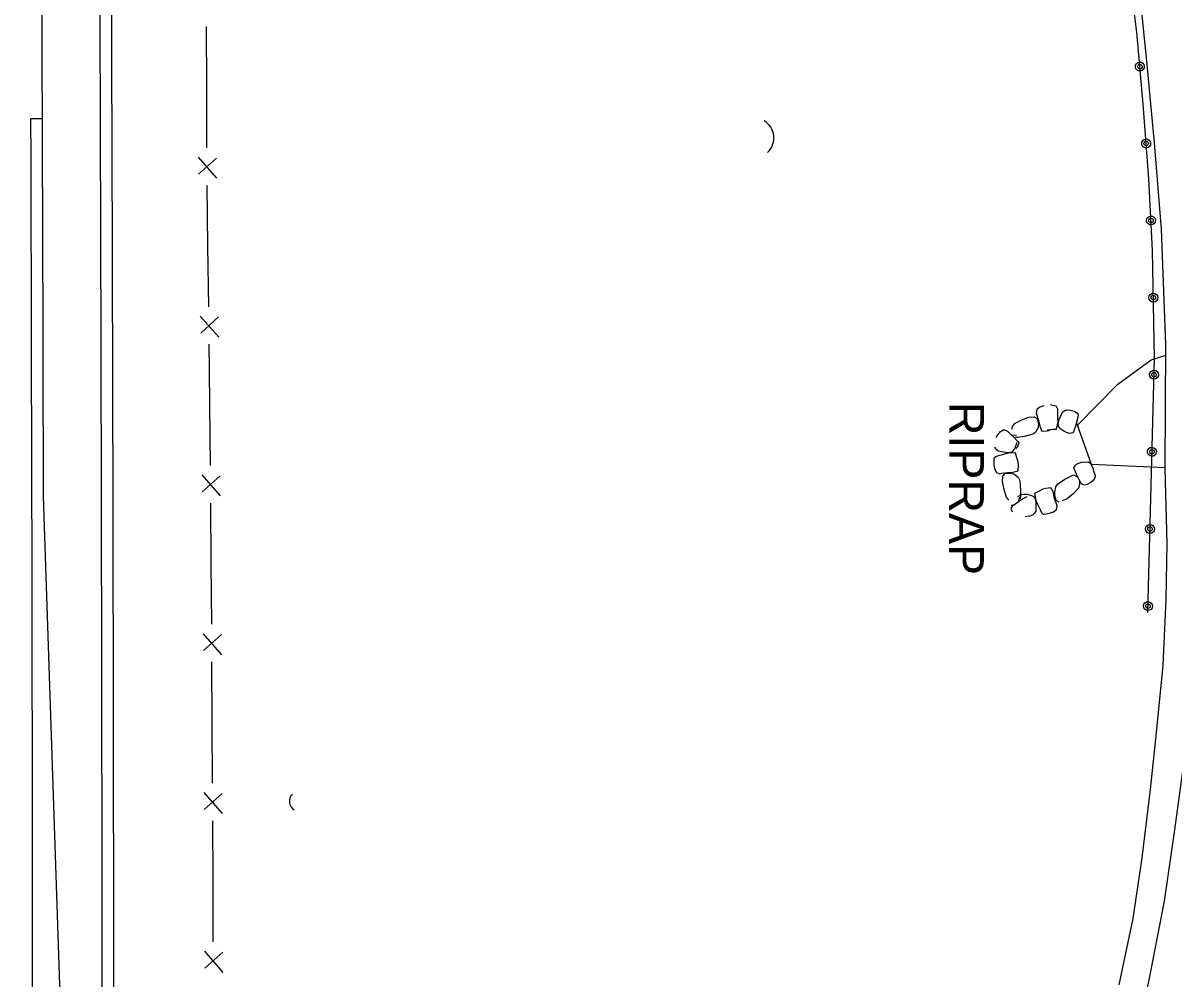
# Model space of a CAD drawing. Extents: x 588843 to 2552415, y 180129 to 269402.
# Drawn here: x 594082.8 to 594281.3, y 188090.9 to 188255.7 of the extents above; entities that cross this region are included whole.
import ezdxf

# ---------------------------------------------------------------- set-up
doc = ezdxf.new("R2010")
doc.units = 0
for name, color, linetype in [('E_BMGRD_P', 7, 'Continuous'), ('E_DRN', 7, 'Continuous'), ('E_DRN_RipRap', 7, 'Continuous'), ('E_DRN_RipRap_Text', 7, 'Continuous'), ('E_FEN_P', 7, 'Continuous'), ('E_RDWY', 7, 'Continuous'), ('E_RDWY_Gravel', 7, 'Continuous'), ('P_RDWY_PavtEdge', 7, 'Continuous'), ('P_RDWY_ShldAgg', 7, 'Continuous'), ('P_RDWY_ShldPaved', 7, 'Continuous')]:
    doc.layers.add(name, color=color, linetype=linetype)

# ---------------------------------------------------------------- blocks, each defined once
blk = doc.blocks.new('CULV2')
at = {"layer": 'E_DRN'}
blk.add_arc((19.7, 14.8), 24.6, 216.8699, 323.1301, dxfattribs=at)
blk = doc.blocks.new('RIPRT')
at = {"layer": 'E_DRN_RipRap_Text'}
blk.add_text('RIPRAP', height=12, dxfattribs=at).set_placement((-0.14, -3.59))

msp = doc.modelspace()

# ---------------------------------------------------------------- linework, layer by layer
at = {"layer": 'E_BMGRD_P'}
msp.add_lwpolyline([(594276.82, 188154.07), (594277.95, 188197.94), (594277.64, 188216.48), (594276.99, 188228.87), (594276.03, 188241.75), (594274.91, 188254.13), (594273.28, 188267.26)], dxfattribs=at)
for centre, major_axis, ratio in [((594275.45, 188248.21), (0.07, -0.772), 0.993246), ((594275.45, 188248.21), (0.035, -0.389), 0.993246), ((594276.54, 188234.95), (0.057, -0.773), 0.993298), ((594276.54, 188234.95), (0.029, -0.389), 0.993298), ((594277.37, 188221.67), (0.04, -0.774), 0.993369), ((594277.37, 188221.67), (0.02, -0.39), 0.993369), ((594277.77, 188208.38), (0.013, -0.775), 0.993497), ((594277.77, 188208.38), (0.007, -0.39), 0.993497), ((594277.88, 188195.08), (-0.023, -0.774), 0.99367), ((594277.88, 188195.08), (-0.012, -0.39), 0.99367), ((594277.53, 188181.78), (-0.023, -0.774), 0.99367), ((594277.53, 188181.78), (-0.012, -0.39), 0.99367), ((594277.19, 188168.48), (-0.023, -0.774), 0.99367), ((594277.19, 188168.48), (-0.012, -0.39), 0.99367), ((594276.85, 188155.18), (-0.023, -0.774), 0.99367), ((594276.85, 188155.18), (-0.012, -0.39), 0.99367)]:
    msp.add_ellipse(centre, major_axis=major_axis, ratio=ratio, dxfattribs=at)
at = {"layer": 'E_DRN_RipRap'}
for p, q in [((594257.66, 188189.07), (594257.55, 188188.45)), ((594257.55, 188188.45), (594257.69, 188188.11)), ((594258.19, 188189.5), (594257.66, 188189.07)), ((594257.69, 188188.11), (594257.99, 188187.16)), ((594258.88, 188189.72), (594258.19, 188189.5)), ((594260.95, 188189.65), (594260.04, 188189.88)), ((594261.08, 188189.57), (594260.95, 188189.65)), ((594261.28, 188189.13), (594261.08, 188189.57)), ((594261.29, 188188.5), (594261.28, 188189.13)), ((594261.32, 188187.63), (594261.29, 188188.5)), ((594261.53, 188187.38), (594261.8, 188187.97)), ((594261.8, 188187.97), (594262.1, 188188.6)), ((594262.1, 188188.6), (594262.4, 188188.84)), ((594262.4, 188188.84), (594262.89, 188189.01)), ((594262.89, 188189.01), (594263.43, 188188.94)), ((594263.43, 188188.94), (594264.14, 188188.79)), ((594264.14, 188188.79), (594264.59, 188188.52)), ((594264.59, 188188.52), (594264.78, 188188.24)), ((594264.78, 188188.24), (594264.77, 188187.74)), ((594253.46, 188186.23), (594253.29, 188185.65)), ((594253.82, 188186.66), (594253.46, 188186.23)), ((594253.82, 188186.66), (594255.09, 188187.32)), ((594255.09, 188187.32), (594256.29, 188187.77)), ((594256.29, 188187.77), (594257.23, 188187.84)), ((594257.23, 188187.84), (594257.74, 188187.52)), ((594257.92, 188186.01), (594257.49, 188185.16)), ((594257.74, 188187.52), (594257.96, 188186.68)), ((594257.96, 188186.68), (594257.92, 188186.01)), ((594257.99, 188187.16), (594258.2, 188186.21)), ((594258.2, 188186.21), (594258.57, 188185.34)), ((594261.09, 188185.71), (594261.35, 188186.95)), ((594261.35, 188186.95), (594261.32, 188187.63)), ((594261.34, 188186.74), (594261.53, 188187.38)), ((594261.4, 188186.19), (594261.34, 188186.74)), ((594261.52, 188186.05), (594261.4, 188186.19)), ((594261.84, 188185.71), (594261.52, 188186.05)), ((594264.37, 188186.2), (594264.08, 188185.41)), ((594264.77, 188187.74), (594264.37, 188186.2)), ((594264.71, 188187.51), (594264.5, 188186.77)), ((594264.84, 188185.98), (594264.5, 188186.77)), ((594250.68, 188184.27), (594250.98, 188184.72)), ((594250.98, 188184.72), (594251.43, 188185.29)), ((594251.43, 188185.29), (594251.86, 188185.56)), ((594251.86, 188185.56), (594252.18, 188185.6)), ((594252.18, 188185.6), (594252.61, 188185.36)), ((594252.61, 188185.36), (594253.76, 188184.26)), ((594252.78, 188185.19), (594253.34, 188184.65)), ((594254.16, 188184.58), (594253.34, 188184.65)), ((594253.76, 188184.26), (594254.32, 188183.63)), ((594254.38, 188184.28), (594253.98, 188184.28)), ((594255.52, 188184.45), (594254.38, 188184.28)), ((594257, 188184.8), (594255.52, 188184.45)), ((594257.49, 188185.16), (594257, 188184.8)), ((594258.57, 188185.34), (594259.47, 188185.43)), ((594259.47, 188185.43), (594260, 188185.53)), ((594259.48, 188185.59), (594260.44, 188185.68)), ((594260.44, 188185.68), (594261.09, 188185.71)), ((594262.32, 188185.33), (594261.84, 188185.71)), ((594262.8, 188185.09), (594262.32, 188185.33)), ((594263.26, 188184.95), (594262.8, 188185.09)), ((594263.93, 188185.05), (594263.26, 188184.95)), ((594264.08, 188185.41), (594263.93, 188185.05)), ((594250.69, 188182.16), (594250.41, 188182.61)), ((594250.99, 188181.92), (594250.69, 188182.16)), ((594253.8, 188182.32), (594253.55, 188181.93)), ((594254.04, 188182.89), (594253.8, 188182.32)), ((594254.35, 188182.67), (594254.03, 188182.33)), ((594254.15, 188183.41), (594254.04, 188182.89)), ((594254.32, 188183.63), (594254.56, 188183.32)), ((594254.56, 188183.32), (594254.35, 188182.67)), ((594250.32, 188180.69), (594250.27, 188180.54)), ((594250.27, 188180.54), (594250.27, 188179.59)), ((594250.68, 188180.99), (594250.32, 188180.69)), ((594251.28, 188181.14), (594250.68, 188180.99)), ((594251.66, 188181.77), (594250.99, 188181.92)), ((594252.1, 188181.36), (594251.28, 188181.14)), ((594252.28, 188181.64), (594251.66, 188181.77)), ((594252.74, 188181.55), (594252.1, 188181.36)), ((594252.94, 188181.59), (594252.28, 188181.64)), ((594253.98, 188181.58), (594252.74, 188181.55)), ((594253.45, 188181.78), (594252.94, 188181.59)), ((594253.55, 188181.93), (594253.45, 188181.78)), ((594254.16, 188180.95), (594253.98, 188181.58)), ((594254.48, 188180.02), (594254.16, 188180.95)), ((594254.49, 188179.47), (594254.48, 188180.02)), ((594265.43, 188179.99), (594266.03, 188180.03)), ((594266.03, 188180.03), (594266.48, 188179.99)), ((594250.27, 188179.59), (594250.37, 188178.84)), ((594250.37, 188178.84), (594250.71, 188178.23)), ((594250.71, 188178.23), (594251.29, 188178.01)), ((594251.29, 188178.01), (594251.64, 188178.1)), ((594251.64, 188178.1), (594252.6, 188178.24)), ((594251.84, 188177.57), (594252.22, 188178.04)), ((594252.22, 188178.04), (594253.06, 188178.13)), ((594252.6, 188178.24), (594253.55, 188178.29)), ((594253.06, 188178.13), (594253.71, 188177.98)), ((594253.55, 188178.29), (594254.44, 188178.53)), ((594254.44, 188178.53), (594254.49, 188179.47)), ((594264.07, 188179.11), (594264.5, 188179.64)), ((594264.19, 188178.74), (594264.07, 188179.11)), ((594264.5, 188177.95), (594264.19, 188178.74)), ((594264.5, 188179.64), (594264.92, 188179.85)), ((594264.92, 188179.85), (594265.43, 188179.99)), ((594266.48, 188179.99), (594266.66, 188179.97)), ((594266.66, 188179.97), (594267.07, 188179.59)), ((594267.07, 188179.59), (594267.34, 188178.98)), ((594267.34, 188178.98), (594267.53, 188178.36)), ((594267.53, 188178.36), (594267.72, 188177.68)), ((594251.77, 188176.61), (594251.84, 188177.57)), ((594252.02, 188175.3), (594251.77, 188176.61)), ((594253.71, 188177.98), (594254.46, 188177.39)), ((594254.46, 188177.39), (594254.73, 188176.82)), ((594254.73, 188176.82), (594254.85, 188175.25)), ((594260.96, 188175.76), (594261.31, 188176.27)), ((594261.31, 188176.27), (594262.6, 188177.11)), ((594262.6, 188177.11), (594263.63, 188177.66)), ((594263.63, 188177.66), (594264.01, 188177.79)), ((594264.01, 188177.79), (594264.77, 188177.43)), ((594265.21, 188176.51), (594264.5, 188177.95)), ((594265.1, 188176.73), (594264.77, 188177.43)), ((594264.91, 188175.59), (594265.12, 188176.12)), ((594265.12, 188176.12), (594265.1, 188176.73)), ((594265.53, 188176.13), (594265.21, 188176.51)), ((594265.84, 188176.06), (594265.53, 188176.13)), ((594266.35, 188176.16), (594265.84, 188176.06)), ((594266.97, 188176.52), (594266.35, 188176.16)), ((594267.41, 188176.83), (594266.97, 188176.52)), ((594267.66, 188177.3), (594267.41, 188176.83)), ((594267.72, 188177.68), (594267.66, 188177.3)), ((594252.46, 188173.89), (594252.02, 188175.3)), ((594254.43, 188174.07), (594255.01, 188174.44)), ((594254.85, 188175.25), (594254.84, 188174.05)), ((594255.01, 188174.44), (594255.48, 188174.5)), ((594255.48, 188174.5), (594256.01, 188174.47)), ((594255.65, 188173.91), (594255.99, 188174.09)), ((594256.01, 188174.47), (594256.6, 188174.31)), ((594256.6, 188174.31), (594257.02, 188174.13)), ((594257.02, 188174.13), (594257.18, 188174.05)), ((594257.86, 188174.9), (594257.28, 188174.61)), ((594257.28, 188174.61), (594257.52, 188173.37)), ((594258.7, 188175.37), (594257.86, 188174.9)), ((594259.23, 188175.47), (594258.7, 188175.37)), ((594260.14, 188175.57), (594259.23, 188175.47)), ((594260.53, 188174.71), (594260.14, 188175.57)), ((594260.75, 188173.76), (594260.53, 188174.71)), ((594260.77, 188174.24), (594260.81, 188174.92)), ((594261.01, 188173.41), (594260.77, 188174.24)), ((594260.81, 188174.81), (594260.96, 188175.76)), ((594263.92, 188174.53), (594262.91, 188173.69)), ((594264.91, 188175.59), (594263.92, 188174.53)), ((594252.46, 188173.89), (594252.82, 188173.45)), ((594253.26, 188172.59), (594253.85, 188172.7)), ((594253.32, 188171.85), (594253.34, 188172.18)), ((594253.34, 188172.18), (594253.66, 188172.56)), ((594253.66, 188172.56), (594254.93, 188173.48)), ((594253.85, 188172.7), (594254.47, 188173.14)), ((594254.69, 188173.96), (594254.47, 188173.14)), ((594254.84, 188174.05), (594254.78, 188173.65)), ((594254.93, 188173.48), (594255.65, 188173.91)), ((594257.18, 188174.05), (594257.45, 188173.56)), ((594257.45, 188173.56), (594257.52, 188172.89)), ((594257.51, 188172.25), (594257.48, 188171.54)), ((594257.52, 188172.89), (594257.51, 188172.25)), ((594257.52, 188173.37), (594257.82, 188172.75)), ((594257.82, 188172.75), (594258.17, 188171.96)), ((594261.05, 188172.81), (594260.75, 188173.76)), ((594261.52, 188173.09), (594261.01, 188173.41)), ((594261.2, 188172.47), (594261.05, 188172.81)), ((594261.09, 188171.85), (594261.2, 188172.47)), ((594262.91, 188173.69), (594262.05, 188173.31)), ((594253.51, 188171.36), (594253.32, 188171.85)), ((594256.39, 188170.69), (594255.68, 188170.55)), ((594256.91, 188170.84), (594256.39, 188170.69)), ((594257.3, 188171.2), (594256.91, 188170.84)), ((594257.48, 188171.54), (594257.3, 188171.2)), ((594258.17, 188171.96), (594258.43, 188171.38)), ((594258.43, 188171.38), (594258.78, 188171.06)), ((594258.78, 188171.06), (594258.93, 188171.03)), ((594258.93, 188171.03), (594259.85, 188171.19)), ((594259.85, 188171.19), (594260.56, 188171.41)), ((594260.56, 188171.41), (594261.09, 188171.85))]:
    msp.add_line(p, q, dxfattribs=at)
at = {"layer": 'E_FEN_P'}
for p, q in [((594113.03, 188232.58), (594116.22, 188228.95)), ((594116.21, 188232.42), (594113.11, 188229.67)), ((594113.37, 188205.18), (594116.59, 188201.58)), ((594116.55, 188205.06), (594113.48, 188202.27)), ((594113.65, 188177.8), (594116.86, 188174.19)), ((594116.83, 188177.66), (594113.74, 188174.9)), ((594113.88, 188150.42), (594117.07, 188146.8)), ((594117.06, 188150.27), (594113.96, 188147.52)), ((594114.02, 188123.04), (594117.21, 188119.41)), ((594117.2, 188122.89), (594114.1, 188120.13)), ((594114.13, 188095.66), (594117.32, 188092.02)), ((594117.31, 188095.5), (594114.21, 188092.75))]:
    msp.add_line(p, q, dxfattribs=at)
for points in [[(594114.42, 188255.1), (594114.46, 188244.65)], [(594114.46, 188244.65), (594114.49, 188234.19)], [(594114.52, 188227.72), (594114.67, 188217.26)], [(594114.67, 188217.26), (594114.81, 188206.81)], [(594114.91, 188200.34), (594114.97, 188195.94), (594115.02, 188189.88)], [(594115.02, 188189.88), (594115.1, 188179.42)], [(594115.16, 188172.95), (594115.25, 188162.5)], [(594115.25, 188162.5), (594115.33, 188152.04)], [(594115.37, 188145.57), (594115.43, 188135.11)], [(594115.43, 188135.11), (594115.48, 188124.66)], [(594115.51, 188118.18), (594115.56, 188108.05), (594115.57, 188107.73)], [(594115.57, 188107.73), (594115.6, 188097.27)]]:
    msp.add_lwpolyline(points, dxfattribs=at)
at = {"layer": 'E_RDWY'}
for points in [[(594274.5, 188078.06), (594277.28, 188091.89), (594279.68, 188104.33), (594281.41, 188116.21), (594283.18, 188129.23), (594284.47, 188141.37), (594285.89, 188155.36), (594286.91, 188169.36), (594287.39, 188181.9), (594287.55, 188193.97), (594287.49, 188205.04), (594287.2, 188215.4), (594286.48, 188227.09), (594285.71, 188238.87), (594284.68, 188249.85), (594282.81, 188262.87), (594280.4, 188274.68), (594277.26, 188286.5), (594273.44, 188299.59), (594268.99, 188312.4), (594262.07, 188329.72), (594256.6, 188342.56), (594251.93, 188353.55), (594249.5, 188358.65)], [(594279.84, 188179.03), (594267.08, 188179.57), (594264.67, 188186.36), (594271.63, 188193.42), (594277.37, 188197.63), (594279.92, 188198.46)]]:
    msp.add_lwpolyline(points, dxfattribs=at)
at = {"layer": 'E_RDWY_Gravel'}
msp.add_lwpolyline([(594271.88, 188089.88), (594274.28, 188101.34), (594275.86, 188111.76), (594277.28, 188123.56), (594278.24, 188132.8), (594279.48, 188144.92), (594279.97, 188156.32), (594280.16, 188166), (594279.84, 188178.9), (594279.93, 188200.3), (594279.16, 188220.18), (594278, 188235.08), (594276.71, 188248.55), (594274.98, 188265.62), (594272.74, 188279.72), (594270.31, 188292.38), (594267.17, 188304.23), (594262.56, 188318.31), (594254.88, 188337.92), (594249.88, 188350.97), (594249.76, 188351.26)], dxfattribs=at)
at = {"layer": 'P_RDWY_PavtEdge'}
for p, q in [((594086.2, 188239.18), (594084.2, 188239.17)), ((594096.29, 187878.74), (594086.37, 188174.07))]:
    msp.add_line(p, q, dxfattribs=at)
for radius, start, end in [(57367.03, 0.124367, 0.6479963), (57365.03, 359.769059, 0.1893986)]:
    msp.add_arc((536719.48, 188049.55), radius, start, end, dxfattribs=at)
at = {"layer": 'P_RDWY_ShldAgg'}
msp.add_arc((536719.48, 188049.55), 57379.03, 0.0014575, 0.2693238, dxfattribs=at)
at = {"layer": 'P_RDWY_ShldPaved'}
msp.add_arc((536719.48, 188049.55), 57377.03, 359.9718622, 0.2693246, dxfattribs=at)

# ---------------------------------------------------------------- block references
at = {"layer": 'E_DRN'}
for p, xscale, yscale, rotation in [((594211.24, 188233.38), 0.13968757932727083, 0.13968757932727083, 95.95335270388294), ((594129.3, 188122.77), 0.0692180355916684, 0.0692180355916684, -83.39145092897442)]:
    msp.add_blockref('CULV2', p, dxfattribs=dict(at, xscale=xscale, yscale=yscale, rotation=rotation))
at = {"layer": 'E_DRN_RipRap_Text', "xscale": 0.5, "yscale": 0.5000000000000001, "rotation": -90.05957280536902}
msp.add_blockref('RIPRT', (594244.37, 188190.33), dxfattribs=at)

doc.saveas('drawing.dxf')
